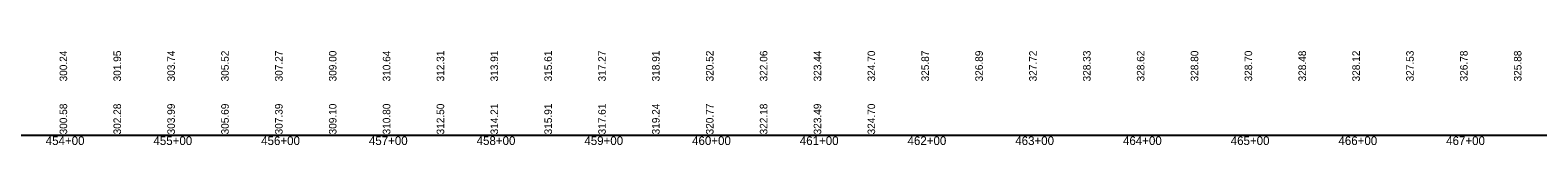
# Model space of a CAD drawing. Extents: x 1876258 to 1926563, y 729739 to 834437.
# Drawn here: x 1923728 to 1925127, y 827954 to 828041 of the extents above; entities that cross this region are included whole.
import ezdxf

# ---------------------------------------------------------------- set-up
doc = ezdxf.new("R2010")
doc.units = 0
for name, color, linetype in [('RD_EX_RailRoad', 7, 'Continuous'), ('RD_PD_ALT3_CL', 7, 'Continuous'), ('RD_PD_Final_Cl', 7, 'Continuous')]:
    doc.layers.add(name, color=color, linetype=linetype)

msp = doc.modelspace()

# ---------------------------------------------------------------- linework, layer by layer
at = {"layer": 'RD_PD_Final_Cl'}
msp.add_line((1878363.1, 827962.8), (1926563.1, 827962.8), dxfattribs=at)

# ---------------------------------------------------------------- texts
at = {"layer": 'RD_EX_RailRoad'}
for s, p in [('300.24', (1923762.1, 828012.8)), ('301.95', (1923812.1, 828012.8)), ('303.74', (1923862.1, 828012.8)), ('305.52', (1923912.1, 828012.8)), ('307.27', (1923962.1, 828012.8)), ('309.00', (1924012.1, 828012.8)), ('310.64', (1924062.1, 828012.8)), ('312.31', (1924112.1, 828012.8)), ('313.91', (1924162.1, 828012.8)), ('315.61', (1924212.1, 828012.8)), ('317.27', (1924262.1, 828012.8)), ('318.91', (1924312.1, 828012.8)), ('320.52', (1924362.1, 828012.8)), ('322.06', (1924412.1, 828012.8)), ('323.44', (1924462.1, 828012.8)), ('324.70', (1924512.1, 828012.8)), ('325.87', (1924562.1, 828012.8)), ('326.89', (1924612.1, 828012.8)), ('327.72', (1924662.1, 828012.8)), ('328.33', (1924712.1, 828012.8)), ('328.62', (1924762.1, 828012.8)), ('328.80', (1924812.1, 828012.8)), ('328.70', (1924862.1, 828012.8)), ('328.48', (1924912.1, 828012.8)), ('328.12', (1924962.1, 828012.8)), ('327.53', (1925012.1, 828012.8)), ('326.78', (1925062.1, 828012.8)), ('325.88', (1925112.1, 828012.8)), ('300.58', (1923762.1, 827963.6)), ('302.28', (1923812.1, 827963.6)), ('303.99', (1923862.1, 827963.6)), ('305.69', (1923912.1, 827963.6)), ('307.39', (1923962.1, 827963.6)), ('309.10', (1924012.1, 827963.6)), ('310.80', (1924062.1, 827963.6)), ('312.50', (1924112.1, 827963.6)), ('314.21', (1924162.1, 827963.6)), ('315.91', (1924212.1, 827963.6)), ('317.61', (1924262.1, 827963.6)), ('319.24', (1924312.1, 827963.6)), ('320.77', (1924362.1, 827963.6)), ('322.18', (1924412.1, 827963.6)), ('323.49', (1924462.1, 827963.6)), ('324.70', (1924512.1, 827963.6))]:
    msp.add_text(s, height=7, rotation=90, dxfattribs=at).set_placement(p)
at = {"layer": 'RD_PD_ALT3_CL'}
for s, p in [('454+00', (1923742.2, 827953.8)), ('455+00', (1923842.2, 827953.8)), ('456+00', (1923942.2, 827953.8)), ('457+00', (1924042.2, 827953.8)), ('458+00', (1924142.2, 827953.8)), ('459+00', (1924242.2, 827953.8)), ('460+00', (1924342.2, 827953.8)), ('461+00', (1924442.2, 827953.8)), ('462+00', (1924542.2, 827953.8)), ('463+00', (1924642.2, 827953.8)), ('464+00', (1924742.2, 827953.8)), ('465+00', (1924842.2, 827953.8)), ('466+00', (1924942.2, 827953.8)), ('467+00', (1925042.2, 827953.8))]:
    msp.add_text(s, height=8, dxfattribs=at).set_placement(p)

doc.saveas('drawing.dxf')
